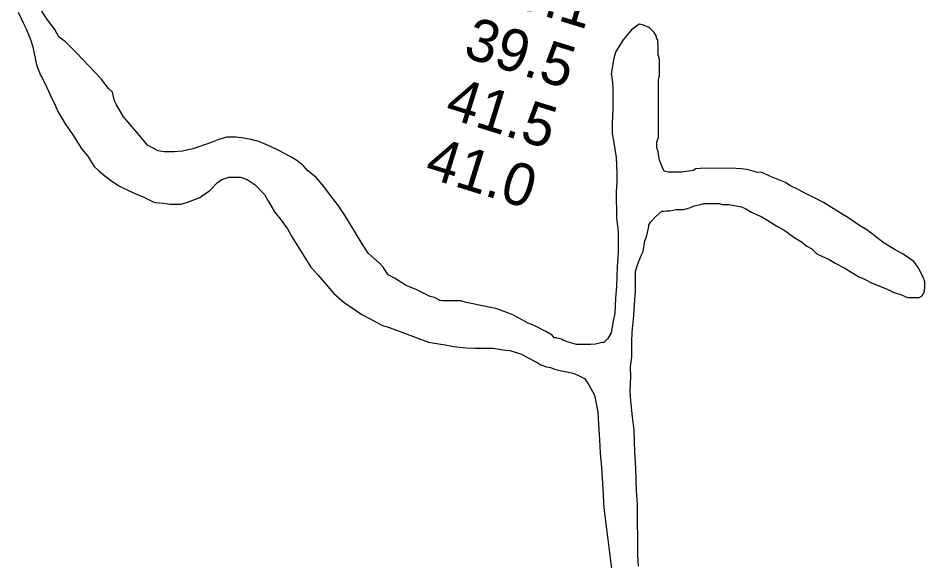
# Model space of a CAD drawing. Extents: x 3146026 to 3183936, y 897894 to 923344.
# Drawn here: x 3151349 to 3152788, y 914176 to 915037 of the extents above; entities that cross this region are included whole.
import ezdxf

# ---------------------------------------------------------------- set-up
doc = ezdxf.new("R2010")
doc.units = 0
doc.layers.add('V-RIVR-RANG', color=7, linetype='Continuous')
doc.layers.add('V-SITE-VEGE', color=7, linetype='Continuous')

msp = doc.modelspace()

# ---------------------------------------------------------------- linework, layer by layer
at = {"layer": 'V-SITE-VEGE'}
for p, q in [((3151394.1, 915036.2), (3151384.3, 915051.2)), ((3151349, 915045.8), (3151357, 915029)), ((3151407.4, 915018.5), (3151394.1, 915036.2)), ((3151357, 915029), (3151362.3, 915018.4)), ((3152334.7, 915026.9), (3152322.3, 915018.1)), ((3152340, 915026), (3152334.7, 915026.9)), ((3152343.5, 915024.3), (3152340, 915026)), ((3152348.8, 915022.5), (3152343.5, 915024.3)), ((3152351.5, 915020.8), (3152348.8, 915022.5)), ((3152358.5, 915013.7), (3152351.5, 915020.8)), ((3151362.3, 915018.4), (3151368.6, 915002.6)), ((3151413.6, 915007.1), (3151407.4, 915018.5)), ((3151424.2, 914999.2), (3151413.6, 915007.1)), ((3152322.3, 915018.1), (3152309.1, 915002.1)), ((3152362.1, 915007.6), (3152358.5, 915013.7)), ((3152362.1, 915004.9), (3152362.1, 915007.6)), ((3152363.9, 915002.3), (3152362.1, 915004.9)), ((3151368.6, 915002.6), (3151372.1, 914991.1)), ((3151372.1, 914991.1), (3151378.4, 914962.8)), ((3151441.9, 914981.5), (3151424.2, 914999.2)), ((3152309.1, 915002.1), (3152297.7, 914983.6)), ((3152364.8, 914988.1), (3152363.9, 915002.3)), ((3151480.9, 914940.1), (3151441.9, 914981.5)), ((3152297.7, 914983.6), (3152294.2, 914972.9)), ((3152364.8, 914978.4), (3152364.8, 914988.1)), ((3152366.6, 914971.3), (3152364.8, 914978.4)), ((3151378.4, 914962.8), (3151384.6, 914946.1)), ((3152294.2, 914972.9), (3152289.8, 914948.2)), ((3152366.7, 914945.7), (3152366.6, 914971.3)), ((3152289.8, 914948.2), (3152291.6, 914939.4)), ((3151384.6, 914946.1), (3151387.3, 914941.7)), ((3151387.3, 914941.7), (3151394.3, 914927.5)), ((3151492.4, 914925.1), (3151480.9, 914940.1)), ((3152291.6, 914939.4), (3152292.5, 914927)), ((3152364.9, 914938.7), (3152366.7, 914945.7)), ((3152365.1, 914847.7), (3152364.9, 914938.7)), ((3151394.3, 914927.5), (3151399.7, 914915.2)), ((3151498.6, 914919), (3151492.4, 914925.1)), ((3151502.1, 914905.7), (3151498.6, 914919)), ((3152292.5, 914927), (3152292.6, 914893.5)), ((3151399.7, 914915.2), (3151407.7, 914898.4)), ((3151504.8, 914900.4), (3151502.1, 914905.7)), ((3151407.7, 914898.4), (3151412.1, 914888.7)), ((3151516.3, 914880.1), (3151504.8, 914900.4)), ((3152292.6, 914893.5), (3152291.8, 914869.6)), ((3151412.1, 914888.7), (3151424.5, 914867.6)), ((3151527, 914867.8), (3151516.3, 914880.1)), ((3151424.5, 914867.6), (3151436, 914851.7)), ((3151544.7, 914846.7), (3151527, 914867.8)), ((3152291.8, 914869.6), (3152291.8, 914853.7)), ((3151436, 914851.7), (3151450.2, 914828.8)), ((3151554.4, 914835.2), (3151544.7, 914846.7)), ((3151679.8, 914847.9), (3151667.4, 914844.3)), ((3151694.8, 914847.9), (3151679.8, 914847.9)), ((3151703.6, 914847), (3151694.8, 914847.9)), ((3151718.7, 914844.4), (3151703.6, 914847)), ((3152291.8, 914853.7), (3152294.5, 914838.7)), ((3152362.5, 914839.8), (3152365.1, 914847.7)), ((3151571.2, 914826.4), (3151554.4, 914835.2)), ((3151635.7, 914832.7), (3151626, 914829.2)), ((3151656.9, 914839.9), (3151635.7, 914832.7)), ((3151667.4, 914844.3), (3151656.9, 914839.9)), ((3151731, 914840.9), (3151718.7, 914844.4)), ((3151749.6, 914833), (3151731, 914840.9)), ((3151763.7, 914826), (3151749.6, 914833)), ((3152294.5, 914838.7), (3152298.1, 914815.8)), ((3152362.5, 914830.9), (3152362.5, 914839.8)), ((3151450.2, 914828.8), (3151459.1, 914818.2)), ((3151459.1, 914818.2), (3151469.7, 914801.4)), ((3151580.1, 914824.7), (3151571.2, 914826.4)), ((3151596.8, 914824.7), (3151580.1, 914824.7)), ((3151610.1, 914825.6), (3151596.8, 914824.7)), ((3151626, 914829.2), (3151610.1, 914825.6)), ((3151780.5, 914817.2), (3151763.7, 914826)), ((3152364.3, 914826.5), (3152362.5, 914830.9)), ((3152367, 914811.5), (3152364.3, 914826.5)), ((3151791.2, 914811), (3151780.5, 914817.2)), ((3151801.8, 914802.2), (3151791.2, 914811)), ((3152298.1, 914815.8), (3152299, 914791)), ((3152371.4, 914800), (3152367, 914811.5)), ((3151469.7, 914801.4), (3151475.9, 914795.3)), ((3151475.9, 914795.3), (3151486.5, 914786.5)), ((3151808, 914795.2), (3151801.8, 914802.2)), ((3151822.1, 914783.7), (3151808, 914795.2)), ((3152299, 914791), (3152299.1, 914776)), ((3152374.1, 914793.9), (3152371.4, 914800)), ((3152380.3, 914792.1), (3152374.1, 914793.9)), ((3152401.5, 914792.2), (3152380.3, 914792.1)), ((3152420, 914794.8), (3152401.5, 914792.2)), ((3152424.4, 914797.5), (3152420, 914794.8)), ((3152431.5, 914798.4), (3152424.4, 914797.5)), ((3152479.2, 914798.5), (3152431.5, 914798.4)), ((3152496.8, 914797.7), (3152479.2, 914798.5)), ((3152505.7, 914796.8), (3152496.8, 914797.7)), ((3152520.7, 914792.4), (3152505.7, 914796.8)), ((3152529.5, 914791.6), (3152520.7, 914792.4)), ((3152542.8, 914785.4), (3152529.5, 914791.6)), ((3151486.5, 914786.5), (3151495.4, 914779.4)), ((3151495.4, 914779.4), (3151508.6, 914770.6)), ((3151652.6, 914763), (3151665, 914775.4)), ((3151665, 914775.4), (3151672, 914780.7)), ((3151672, 914780.7), (3151683.5, 914784.3)), ((3151683.5, 914784.3), (3151702, 914784.3)), ((3151702, 914784.3), (3151712.6, 914780.8)), ((3151712.6, 914780.8), (3151725, 914772)), ((3151831.9, 914772.3), (3151822.1, 914783.7)), ((3152299.1, 914776), (3152298.2, 914761.9)), ((3152566.6, 914775.8), (3152542.8, 914785.4)), ((3152573.7, 914771.4), (3152566.6, 914775.8)), ((3151508.6, 914770.6), (3151513.9, 914768)), ((3151513.9, 914768), (3151533.4, 914759.2)), ((3151642, 914755.9), (3151652.6, 914763)), ((3151725, 914772), (3151740.1, 914757)), ((3151846.9, 914752.9), (3151831.9, 914772.3)), ((3152298.2, 914761.9), (3152298.3, 914719.5)), ((3152587.9, 914764.3), (3152573.7, 914771.4)), ((3152597.6, 914759.1), (3152587.9, 914764.3)), ((3151533.4, 914759.2), (3151547.5, 914753)), ((3151547.5, 914753), (3151559.9, 914746.9)), ((3151559.9, 914746.9), (3151566.1, 914744.3)), ((3151619.1, 914745.3), (3151637.6, 914752.4)), ((3151637.6, 914752.4), (3151642, 914755.9)), ((3151740.1, 914757), (3151746.3, 914745.6)), ((3151857.6, 914738.8), (3151846.9, 914752.9)), ((3152611.7, 914752), (3152597.6, 914759.1)), ((3152626.8, 914744.1), (3152611.7, 914752)), ((3151566.1, 914744.3), (3151580.2, 914743.4)), ((3151580.2, 914743.4), (3151590, 914741.7)), ((3151590, 914741.7), (3151607.6, 914741.7)), ((3151607.6, 914741.7), (3151619.1, 914745.3)), ((3151746.3, 914745.6), (3151756, 914729.7)), ((3151868.2, 914722.9), (3151857.6, 914738.8)), ((3152383.1, 914731.2), (3152392.8, 914733)), ((3152392.8, 914733), (3152405.1, 914733)), ((3152405.1, 914733), (3152415.7, 914736.5)), ((3152415.7, 914736.5), (3152421.9, 914739.2)), ((3152421.9, 914739.2), (3152431.6, 914741)), ((3152431.6, 914741), (3152436.9, 914742.8)), ((3152436.9, 914742.8), (3152461.6, 914742.8)), ((3152461.6, 914742.8), (3152466.9, 914741.1)), ((3152466.9, 914741.1), (3152476.7, 914741.1)), ((3152476.7, 914741.1), (3152485.5, 914739.4)), ((3152485.5, 914739.4), (3152497, 914737.6)), ((3152497, 914737.6), (3152504, 914734.1)), ((3152504, 914734.1), (3152512.9, 914728.8)), ((3152650.7, 914729.2), (3152626.8, 914744.1)), ((3151756, 914729.7), (3151764.9, 914718.2)), ((3151764.9, 914718.2), (3151776.4, 914702.4)), ((3151894.8, 914678.8), (3151868.2, 914722.9)), ((3152298.3, 914719.5), (3152301, 914698.3)), ((3152353.1, 914713.4), (3152361, 914722.3)), ((3152361, 914722.3), (3152370.7, 914730.3)), ((3152370.7, 914730.3), (3152373.3, 914730.3)), ((3152373.3, 914730.3), (3152377.8, 914731.2)), ((3152377.8, 914731.2), (3152383.1, 914731.2)), ((3152512.9, 914728.8), (3152520.8, 914725.3)), ((3152520.8, 914725.3), (3152527.9, 914721.8)), ((3152527.9, 914721.8), (3152536.8, 914716.5)), ((3152665.7, 914720.4), (3152650.7, 914729.2)), ((3152684.3, 914708), (3152665.7, 914720.4)), ((3152346.1, 914689.6), (3152349.6, 914706.4)), ((3152349.6, 914709), (3152353.1, 914713.4)), ((3152349.6, 914706.4), (3152349.6, 914709)), ((3152536.8, 914716.5), (3152552.7, 914706.8)), ((3152552.7, 914706.8), (3152564.2, 914700.7)), ((3152695.8, 914701), (3152684.3, 914708)), ((3151776.4, 914702.4), (3151782.6, 914690.9)), ((3151782.6, 914690.9), (3151813.6, 914641.5)), ((3152301, 914698.3), (3152301.1, 914664.7)), ((3152343.4, 914683.4), (3152346.1, 914689.6)), ((3152564.2, 914700.7), (3152580.1, 914689.2)), ((3152580.1, 914689.2), (3152590.7, 914683.1)), ((3152723.2, 914679.9), (3152695.8, 914701)), ((3151904.6, 914663.8), (3151894.8, 914678.8)), ((3152340.8, 914666.6), (3152343.4, 914683.4)), ((3152590.7, 914683.1), (3152600.4, 914675.2)), ((3152600.4, 914675.2), (3152608.4, 914670.8)), ((3152740.9, 914669.3), (3152723.2, 914679.9)), ((3151922.3, 914648), (3151904.6, 914663.8)), ((3152301.1, 914664.7), (3152299.4, 914642.7)), ((3152335.5, 914655.1), (3152338.2, 914661.3)), ((3152338.2, 914661.3), (3152340.8, 914666.6)), ((3152608.4, 914670.8), (3152616.4, 914662.8)), ((3152616.4, 914662.8), (3152624.3, 914659.3)), ((3152753.3, 914662.3), (3152740.9, 914669.3)), ((3152770.1, 914650.8), (3152753.3, 914662.3)), ((3151928.4, 914641.8), (3151922.3, 914648)), ((3152331.2, 914643.6), (3152334.7, 914652.5)), ((3152334.7, 914652.5), (3152335.5, 914655.1)), ((3152624.3, 914659.3), (3152635.8, 914654.1)), ((3152635.8, 914654.1), (3152645.6, 914647.9)), ((3152645.6, 914647.9), (3152659.7, 914640.9)), ((3152777.2, 914641.1), (3152770.1, 914650.8)), ((3151813.6, 914641.5), (3151825.1, 914629.2)), ((3151936.4, 914629.4), (3151928.4, 914641.8)), ((3152299.4, 914642.7), (3152298.6, 914610.9)), ((3152328.5, 914634.8), (3152331.2, 914643.6)), ((3152328.6, 914603.9), (3152328.5, 914634.8)), ((3152659.7, 914640.9), (3152669.4, 914634.7)), ((3152669.4, 914634.7), (3152682.7, 914626.8)), ((3152785.1, 914626.1), (3152777.2, 914641.1)), ((3151825.1, 914629.2), (3151849.9, 914600.1)), ((3151946.2, 914624.2), (3151936.4, 914629.4)), ((3151964.7, 914612.7), (3151946.2, 914624.2)), ((3152682.7, 914626.8), (3152693.3, 914622.4)), ((3152693.3, 914622.4), (3152703, 914617.1)), ((3152703, 914617.1), (3152717.2, 914611)), ((3152787.8, 914618.2), (3152785.1, 914626.1)), ((3152787.8, 914611.1), (3152787.8, 914618.2)), ((3151981.5, 914605.7), (3151964.7, 914612.7)), ((3152002.7, 914595.2), (3151981.5, 914605.7)), ((3152298.6, 914610.9), (3152296.8, 914592.3)), ((3152326.9, 914582.7), (3152328.6, 914603.9)), ((3152717.2, 914611), (3152726.9, 914607.5)), ((3152726.9, 914607.5), (3152738.4, 914601.3)), ((3152783.4, 914596.1), (3152787, 914603.2)), ((3152787, 914603.2), (3152787.8, 914611.1)), ((3151849.9, 914600.1), (3151866.8, 914585.1)), ((3152009.8, 914593.4), (3152002.7, 914595.2)), ((3152018.7, 914589), (3152009.8, 914593.4)), ((3152022.2, 914588.1), (3152018.7, 914589)), ((3152051.3, 914588.2), (3152022.2, 914588.1)), ((3152060.2, 914585.6), (3152051.3, 914588.2)), ((3152296.8, 914592.3), (3152296, 914568.5)), ((3152738.4, 914601.3), (3152748.1, 914598.7)), ((3152748.1, 914598.7), (3152760.5, 914593.4)), ((3152760.5, 914593.4), (3152779, 914593.5)), ((3152779, 914593.5), (3152783.4, 914596.1)), ((3151866.8, 914585.1), (3151877.4, 914578.1)), ((3151877.4, 914578.1), (3151894.2, 914566.6)), ((3152093.7, 914578.6), (3152060.2, 914585.6)), ((3152107, 914576), (3152093.7, 914578.6)), ((3152124.7, 914569.8), (3152107, 914576)), ((3152326, 914565), (3152326.9, 914582.7)), ((3151894.2, 914566.6), (3151906.6, 914560.5)), ((3151906.6, 914560.5), (3151926, 914549.9)), ((3152135.3, 914565.4), (3152124.7, 914569.8)), ((3152158.3, 914553.1), (3152135.3, 914565.4)), ((3152296, 914568.5), (3152293.4, 914556.1)), ((3152323.5, 914538.5), (3152326, 914565)), ((3151926, 914549.9), (3151939.3, 914545.5)), ((3151939.3, 914545.5), (3151962.3, 914536.8)), ((3152168.9, 914548.7), (3152158.3, 914553.1)), ((3152186.6, 914539.9), (3152168.9, 914548.7)), ((3152293.4, 914556.1), (3152289.9, 914537.5)), ((3151962.3, 914536.8), (3152000.3, 914522.7)), ((3152196.3, 914533.8), (3152186.6, 914539.9)), ((3152199.8, 914529.4), (3152196.3, 914533.8)), ((3152289.9, 914537.5), (3152284.6, 914528.7)), ((3152322.6, 914522.6), (3152323.5, 914538.5)), ((3152000.3, 914522.7), (3152006.4, 914521.9)), ((3152006.4, 914521.9), (3152026.8, 914518.4)), ((3152026.8, 914518.4), (3152040, 914515.8)), ((3152040, 914515.8), (3152060.3, 914514)), ((3152202.5, 914529.4), (3152199.8, 914529.4)), ((3152206, 914528.5), (3152202.5, 914529.4)), ((3152211.3, 914527.6), (3152206, 914528.5)), ((3152214, 914525.9), (3152211.3, 914527.6)), ((3152220.2, 914523.2), (3152214, 914525.9)), ((3152235.2, 914518.9), (3152220.2, 914523.2)), ((3152257.3, 914518.9), (3152235.2, 914518.9)), ((3152265.2, 914519.8), (3152257.3, 914518.9)), ((3152275.8, 914522.5), (3152265.2, 914519.8)), ((3152278.5, 914522.5), (3152275.8, 914522.5)), ((3152284.6, 914528.7), (3152278.5, 914522.5)), ((3152322.7, 914499.6), (3152322.6, 914522.6)), ((3152060.3, 914514), (3152073.6, 914513.2)), ((3152073.6, 914513.2), (3152102.7, 914513.3)), ((3152102.7, 914513.3), (3152118.6, 914510.6)), ((3152118.6, 914510.6), (3152129.2, 914509.8)), ((3152129.2, 914509.8), (3152147.8, 914503.6)), ((3152147.8, 914503.6), (3152157.5, 914498.4)), ((3152157.5, 914498.4), (3152171.7, 914491.3)), ((3152171.7, 914491.3), (3152178.7, 914486.9)), ((3152178.7, 914486.9), (3152187.6, 914483.4)), ((3152320.9, 914483.7), (3152322.7, 914499.6)), ((3152187.6, 914483.4), (3152193.8, 914482.6)), ((3152193.8, 914482.6), (3152200, 914479.9)), ((3152200, 914479.9), (3152211.4, 914477.3)), ((3152211.4, 914477.3), (3152217.6, 914476.4)), ((3152217.6, 914476.4), (3152229.1, 914473.8)), ((3152229.1, 914473.8), (3152236.2, 914471.2)), ((3152321, 914467.8), (3152320.9, 914483.7)), ((3152236.2, 914471.2), (3152247.7, 914465)), ((3152247.7, 914465), (3152254.8, 914455.3)), ((3152320.1, 914444.9), (3152321, 914467.8)), ((3152254.8, 914455.3), (3152263.6, 914438.6)), ((3152321.1, 914429), (3152320.1, 914444.9)), ((3152263.6, 914438.6), (3152269, 914412.1)), ((3152323.8, 914404.3), (3152321.1, 914429)), ((3152269, 914412.1), (3152269.9, 914392.7)), ((3152326.5, 914383.1), (3152323.8, 914404.3)), ((3152269.9, 914392.7), (3152271.8, 914367.9)), ((3152327.4, 914347.8), (3152326.5, 914383.1)), ((3152271.8, 914367.9), (3152272.7, 914346.7)), ((3152272.7, 914346.7), (3152274.5, 914323.8)), ((3152329.3, 914323), (3152327.4, 914347.8)), ((3152274.5, 914323.8), (3152276.3, 914299.1)), ((3152330.2, 914287.7), (3152329.3, 914323)), ((3152276.3, 914299.1), (3152278.2, 914260.2)), ((3152332.1, 914265.6), (3152330.2, 914287.7)), ((3152278.2, 914260.2), (3152284.5, 914209.9)), ((3152332.2, 914184.4), (3152332.1, 914265.6)), ((3152284.5, 914209.9), (3152290.8, 914164)), ((3152333.2, 914167.6), (3152332.2, 914184.4))]:
    msp.add_line(p, q, dxfattribs=at)

# ---------------------------------------------------------------- texts
at = {"layer": 'V-RIVR-RANG'}
for s, p in [('29.1', (3152084.9, 915070.7)), ('39.5', (3152053.2, 914975.8)), ('41.5', (3152023.8, 914880.3)), ('41.0', (3151991.6, 914785.6))]:
    msp.add_text(s, height=67, rotation=342.7483, dxfattribs=at).set_placement(p)

doc.saveas('drawing.dxf')
